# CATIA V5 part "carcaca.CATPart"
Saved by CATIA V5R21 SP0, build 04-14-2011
Part number: carcaça
Material "Grey Blue": density 7860 kg/m3, Young's modulus 2e+11 Pa, Poisson ratio 0.266
Bounding box of the stored display mesh (mm): x -290 to 290, y -552.604 to 1061.459, z 20.422 to 226.308
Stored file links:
  C:\Users\rodri\OneDrive\Área de Trabalho\FACULDADE\3°semestre\Sistemas Aeroespaciais\Projeto de avião 2019-02\CAD\carcaca.CATPart
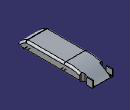
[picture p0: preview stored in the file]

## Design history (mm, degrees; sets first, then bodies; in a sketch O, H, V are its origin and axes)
Body1 (main body), material "Grey Blue"
  Sketch1 on yz-plane, origin (0, 0, 0), H (0, 1, 0), V (0, 0, 1)
    spline S1 through (-438.5408, 20.4222) (-544.7902, 60.5912) (-380.1484, 220.4222)
    point P1 (-438.5408, 20.4222)
    point P2 (1061.4592, 20.4222)
    line L1 (1061.4592, 20.4222) -> (-438.5408, 20.4222)
    axis line L2 (-676.0826, 141.5999) -> (1522.6222, 141.5999)
    line L3 (-380.1484, 220.4222) -> (457.451, 220.4222)
    point P5 (457.451, 220.4222)
    point P6 (-380.1484, 220.4222)
    spline S2 through (457.451, 220.4222) (645.3508, 220.4222) (1061.4592, 20.4222)
    point P7 (-380.1484, 220.4222)
    point P8 (-438.5408, 20.4222)
    point P9 (-544.7902, 60.5912)
    point P10 (457.451, 220.4222)
    point P11 (645.3508, 220.4222)
    point P12 (1061.4592, 20.4222)
    length L1 = 1500
    distance P9 V = 544.7902
    distance L3 L1 = 200
    horizontal: L2 H, L3 H
    coincidence: P8 P1, P7 P6, P10 P5, P11 L3, P12 P2
  Pad1: profile Sketch1, direction (1, 0, 0), length 250, mirrored extent
  Sketch2 on face of Pad1 from Sketch1.L3, origin (0, 0, 220.4222), H (1, 0, 0), V (0, 1, 0)
    point P1 (175, 1300)
    line L1 (175, 1300) -> (543.622, 1300)
    line L2 (543.622, 1300) -> (543.622, 800)
    line L3 (543.622, 800) -> (175, 800)
    line L4 (175, 800) -> (175, 1300)
    point P2 (543.622, 1300)
    point P3 (543.622, 800)
    point P4 (175, 800)
    point P5 (-543.622, 1300)
    point P6 (-175, 1300)
    line L5 (-175, 1300) -> (-543.622, 1300)
    point P7 (-175, 800)
    line L6 (-175, 800) -> (-175, 1300)
    point P8 (-543.622, 800)
    line L7 (-543.622, 1300) -> (-543.622, 800)
    line L8 (-543.622, 800) -> (-175, 800)
    reference projected line E1 (250, 457.451) -> (250, -380.1484) from edge [face of Pad1 from Sketch1.L3 | end face of Pad1]
    length L3 = 368.622
    length L2 = 500
    distance H L3 = 800
    distance E1 L4 = 75
    horizontal: L1 H, L3 H
    vertical: L2 V, L4 V
    symmetry: P2 P5 V, P1 P6 V, L1 L5 V, P4 P7 V, L4 L6 V, P3 P8 V, L2 L7 V, L3 L8 V
  Pocket1: profile Sketch2, direction (0, 0, -1), through (limit type 3)
  Fillet1: radius 40, on edge [start face of Pad1 | face of Pad1 from Sketch1.L3]
  Fillet2: radius 40, on edge [face of Pad1 from Sketch1.L3 | end face of Pad1]
  Sketch3 on end face of Pad1, origin (250, 0, 0), H (0, 1, 0), V (0, 0, 1)
    circle A1 centre (500, 120.4222) radius 5
    point P1 (500, 120.4222)
    circle A2 centre (439.97, 120.4222) radius 5
    point P2 (439.97, 120.4222)
    reference projected line E1 (800, 182.1512) -> (800, 20.4222) from edge [end face of Pad1 | face of Pocket1 from Sketch2.L3]
    reference projected line E2 (457.451, 220.4222) -> (-380.1484, 220.4222) from edge [face of Pad1 from Sketch1.L3 | face of Fillet2]
    reference projected line E3 (457.451, 220.4222) -> (-380.1484, 220.4222) from edge [face of Pad1 from Sketch1.L3 | face of Fillet2]
    circle A3 centre (-350, 120.4222) radius 5
    point P3 (-350, 120.4222)
    reference projected line E4 (800, 182.1512) -> (800, 20.4222) from edge [end face of Pad1 | face of Pocket1 from Sketch2.L3]
    reference projected line E5 (457.451, 220.4222) -> (-380.1484, 220.4222) from edge [face of Pad1 from Sketch1.L3 | face of Fillet2]
    circle A4 centre (-289.97, 120.4222) radius 5
    point P4 (-289.97, 120.4222)
    reference projected line E6 (457.451, 220.4222) -> (-380.1484, 220.4222) from edge [face of Pad1 from Sketch1.L3 | face of Fillet2]
    distance P1 E1 = 300
    distance P2 P1 = 60.03
    radius A2 = 5
    radius A1 = 5
    distance P1 E2 = 100
    distance P2 E3 = 100
    distance P3 E4 = 1150
    distance P3 E5 = 100
    distance P4 E6 = 100
    distance P3 P4 = 60.03
    radius A4 = 5
    radius A3 = 5
  Pad2: profile Sketch3, direction (1, 0, 0), length 40
  Mirror1: of Pad2, about yz-plane
  Fillet3: radius 40, on edge [face of Pocket1 from Sketch2.L3 | face of Pocket1 from Sketch2.L4]
  Fillet4: radius 40, on edge [face of Pocket1 from Sketch2.L6 | face of Pocket1 from Sketch2.L8]
  Fillet5: radius 40, on edge [start face of Pad1 | face of Pad1 from Sketch1.S2]
  Fillet6: radius 40, on edge [face of Pad1 from Sketch1.S2 | end face of Pad1]
  Fillet7: radius 40, on edge [face of Pad1 from Sketch1.L3 | face of Pad1 from Sketch1.S2]
  Fillet8: radius 40, on edge [face of Pad1 from Sketch1.S1 | face of Pad1 from Sketch1.L3]
  Fillet9: radius 40, on edge [face of Pad1 from Sketch1.L1 | end face of Pad1]; edge [face of Pad1 from Sketch1.L1 | face of Fillet8]
  Sketch4 on face of Pocket1 from Sketch2.L4, origin (175, 0, 0), H (0, 1, 0), V (0, 0, 1)
    line L1 (930, 45.4222) -> (1032.3301, 45.4222)
    line L2 (1061.4592, 20.4222) -> (930, 20.4222)
    line L3 (930, 20.4222) -> (930, 45.4222)
    reference projected line E1 (800, 20.4222) -> (1061.4592, 20.4222) from edge [face of Pad1 from Sketch1.L1 | face of Pocket1 from Sketch2.L4]
    line L4 (1032.3301, 45.4222) -> (1061.4592, 20.4222)
    length L3 = 25
    length L2 = 131.4592
    horizontal: L1 H, L2 H
    vertical: L3 V
    coincidence: L2 E1
  Pad3: profile Sketch4, direction (1, 0, 0), length 400, mirrored extent
  Sketch5 on face of Pad3 from Sketch4.L1, origin (0, 0, 45.4222), H (1, 0, 0), V (0, 1, 0)
    reference projected line E1 (-225, 1032.3301) -> (-225, 930) from edge [start face of Pad3 | face of Pad3 from Sketch4.L1]
    reference projected line E2 (-175, 930) -> (-175, 1032.3301) from edge [face of Pocket1 from Sketch2.L6 | face of Pad3 from Sketch4.L1]
    reference projected line E3 (175, 800) -> (175, 1061.4592) from edge [face of Pocket1 from Sketch2.L4 | face of Pad1 from Sketch1.S2]
    reference projected line E4 (575, 1032.3301) -> (575, 930) from edge [face of Pad3 from Sketch4.L1 | end face of Pad3]
    line L1 (225, 1188.2113) -> (625, 1188.2113)
    line L2 (625, 1188.2113) -> (625, 862.2509)
    line L3 (625, 862.2509) -> (225, 862.2509)
    line L4 (225, 862.2509) -> (225, 1188.2113)
    reference projected line E5 (175, 800) -> (175, 1061.4592) from edge [face of Pocket1 from Sketch2.L4 | face of Pad1 from Sketch1.S2]
    distance E1 E2 = 50 (reference)
    distance E3 E4 = 400 (reference)
    distance E5 L4 = 50
    length L3 = 400
    horizontal: L1 H, L3 H
    vertical: L2 V, L4 V
  Pocket2: profile Sketch5, direction (0, 0, -1), through (limit type 3)
  Sketch6 on face of Pocket2 from Sketch5.L4, origin (225, 0, 0), H (0, 1, 0), V (0, 0, 1)
    line L1 (930, 20.4222) -> (930, 170.4222)
    line L2 (930, 170.4222) -> (1061.459, 170.4222)
    line L3 (1061.459, 170.4222) -> (1061.459, 20.4222)
    line L4 (1061.459, 20.4222) -> (930, 20.4222)
    reference projected line E1 (930, 20.4222) -> (1061.4592, 20.4222) from edge [face of Pad3 | face of Pocket2 from Sketch5.L4]
    reference projected line E2 (930, 45.4222) -> (930, 20.4222) from edge [face of Pad3 from Sketch4.L3 | face of Pocket2 from Sketch5.L4]
    length L4 = 131.459
    length L3 = 150
    vertical: L1 V, L3 V
    horizontal: L2 H, L4 H
    coincidence: L4 E1, L1 E2
  Pad4: profile Sketch6, direction (-1, 0, 0), length 20
  Fillet10: radius 10, on edge [face of Pad3 from Sketch4.L4 | end face of Pad4]
  Fillet11: radius 10, on edge [face of Pad3 from Sketch4.L1 | end face of Pad4]
  Fillet12: radius 10, on edge [face of Pad3 from Sketch4.L1 | face of Pad3 from Sketch4.L4]
  Mirror2: of the body so far, about yz-plane
  Fillet13: radius 5, on edge [face of Mirror2 | face of Pad4 from Sketch6.L3]; edge [face of Mirror2 | face of Mirror2] (x2); edge [face of Pad3 | face of Mirror2] (x2)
